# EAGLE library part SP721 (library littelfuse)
SP721 - TVS Diode Array Transient Voltage Suppressor 6 per package
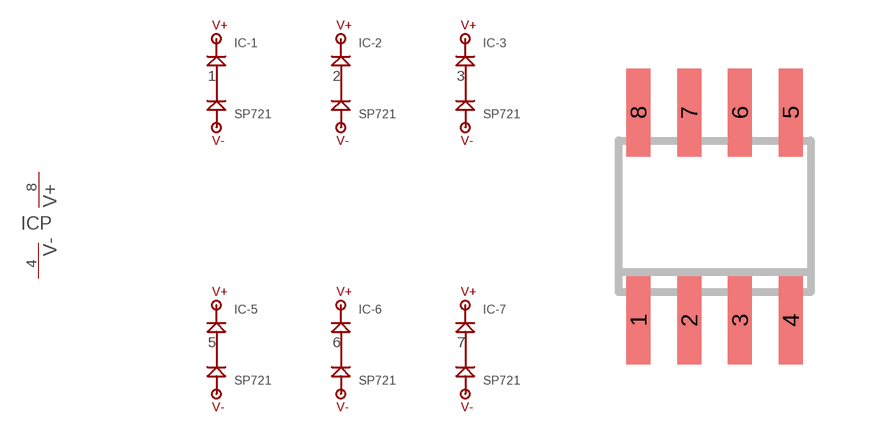
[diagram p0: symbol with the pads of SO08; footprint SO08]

Designator prefix IC; gates P=VDD-VSS -1=TVS -2=TVS -3=TVS -5=TVS -6=TVS -7=TVS

## SP721AB  [SO08]
1  -1:IN  pas
2  -2:IN  pas
3  -3:IN  pas
4  P:V-  pwr
5  -5:IN  pas
6  -6:IN  pas
7  -7:IN  pas
8  P:V+  pwr

## Footprint SO08 (pad centres in mm)
Small Outline Package 8 NS Package M08A
smd 0.6 x 2.2: 1 -1.905,-2.6; 2 -0.635,-2.6; 3 0.635,-2.6; 4 1.905,-2.6; 5 1.905,2.6; 6 0.635,2.6; 7 -0.635,2.6; 8 -1.905,2.6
